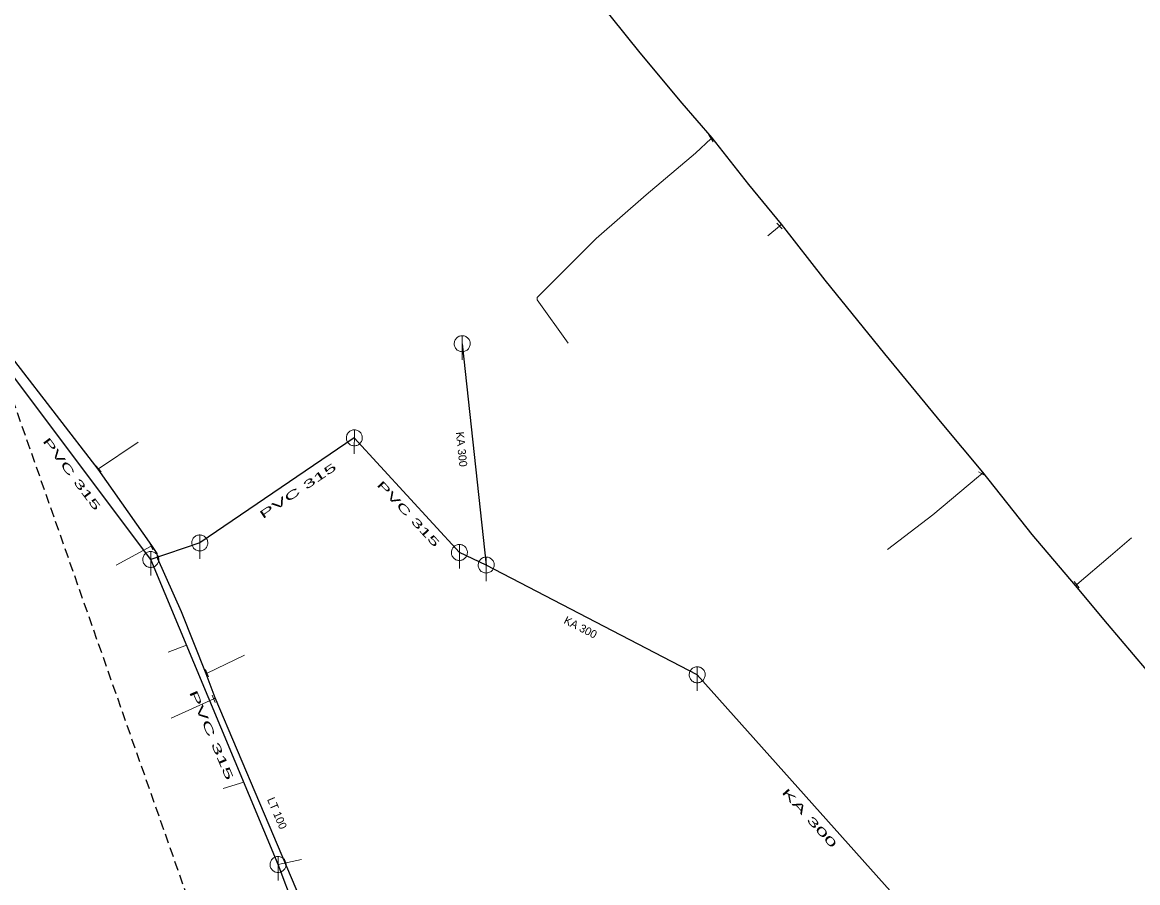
# Model space of a CAD drawing. Extents: x -659250 to -657316, y -997555 to -993684.
# Drawn here: x -658240.4 to -658101, y -996407.1 to -996299.7 of the extents above; entities that cross this region are included whole.
import ezdxf

# ---------------------------------------------------------------- set-up
doc = ezdxf.new("R2010")
doc.units = 0
doc.header["$LTSCALE"] = 0.4
doc.linetypes.add('MEDIUM_DASHED', pattern=[4.5, 3, -1.5])
doc.layers.add('1', color=7, linetype='Continuous')
for name, color, linetype, lineweight in [('11', 7, 'Continuous', 13), ('13', 7, 'Continuous', 13), ('14', 7, 'Continuous', 25), ('17', 7, 'Continuous', 25), ('22', 7, 'Continuous', 13), ('34', 7, 'Continuous', 13), ('63', 7, 'MEDIUM_DASHED', 25)]:
    doc.layers.add(name, color=color, linetype=linetype, lineweight=lineweight)

msp = doc.modelspace()

# ---------------------------------------------------------------- linework, layer by layer
at = {"layer": '11'}
for p, q in [((-658222.111, -996378.361), (-658219.838, -996377.453)), ((-658215.245, -996395.376), (-658212.681, -996394.592)), ((-658205.449, -996404.236), (-658208.39, -996404.87))]:
    msp.add_line(p, q, dxfattribs=at)
at = {"layer": '13'}
for p, q in [((-658145.723, -996325.114), (-658147.197, -996326.344)), ((-658230.833, -996355.452), (-658225.859, -996352.096)), ((-658224.251, -996365.11), (-658228.635, -996367.46)), ((-658217.266, -996380.958), (-658212.598, -996378.71)), ((-658216.432, -996384.188), (-658221.767, -996386.589))]:
    msp.add_line(p, q, dxfattribs=at)
for points in [[(-658154.274, -996314.158), (-658156.236, -996315.995), (-658162.373, -996321.204), (-658168.644, -996326.682), (-658176.017, -996334.056), (-658176.017, -996334.337), (-658172.149, -996339.734)], [(-658120.421, -996356.066), (-658120.874, -996356.386), (-658126.546, -996361.206), (-658132.236, -996365.537)], [(-658108.579, -996369.897), (-658104.349, -996366.303), (-658101.715, -996364.07)]]:
    msp.add_lwpolyline(points, dxfattribs=at)
at = {"layer": '14', "lineweight": 13}
for p, q in [((-658154.151, -996314.079), (-658154.274, -996314.158)), ((-658145.489, -996324.896), (-658145.723, -996325.114)), ((-658230.887, -996355.498), (-658230.834, -996355.452)), ((-658120.304, -996355.87), (-658120.421, -996356.066)), ((-658224.153, -996365.028), (-658224.251, -996365.11)), ((-658108.715, -996370.004), (-658108.579, -996369.897)), ((-658217.364, -996381.052), (-658217.266, -996380.958)), ((-658216.25, -996384.063), (-658216.432, -996384.188))]:
    msp.add_line(p, q, dxfattribs=at)
at = {"layer": '14'}
for p, q in [((-658224.3, -996366.77), (-658244.07, -996340.44)), ((-658218.17, -996364.699), (-658224.3, -996366.77)), ((-658208.39, -996404.87), (-658224.3, -996366.77)), ((-658156.01, -996381.17), (-658182.379, -996367.46)), ((-658192.724, -996446.332), (-658208.39, -996404.87))]:
    msp.add_line(p, q, dxfattribs=at)
for points in [[(-658185.379, -996339.809), (-658182.379, -996367.46), (-658185.73, -996365.89)], [(-658185.73, -996365.89), (-658198.859, -996351.57), (-658218.17, -996364.699)], [(-658102.699, -996440.03), (-658128.059, -996412.449), (-658156.01, -996381.17)]]:
    msp.add_lwpolyline(points, dxfattribs=at)
at = {"layer": '17'}
for points in [[(-658099.838, -996380.568), (-658104.721, -996374.813), (-658108.715, -996370.004), (-658114.16, -996363.631), (-658120.304, -996355.87), (-658125.403, -996349.761), (-658132.55, -996341.083), (-658140.008, -996331.868), (-658145.489, -996324.896), (-658149.55, -996319.91), (-658154.151, -996314.079), (-658157.877, -996309.767), (-658163.125, -996303.473), (-658168.581, -996296.64)], [(-658187.677, -996452.73), (-658187.756, -996452.037), (-658193.366, -996439.601), (-658202.822, -996415.717), (-658204.513, -996411.723), (-658210.651, -996397.227), (-658216.25, -996384.063), (-658217.364, -996381.052), (-658220.46, -996373.316), (-658223.436, -996366.695), (-658223.489, -996366.02), (-658224.153, -996365.028), (-658230.886, -996355.498), (-658241.289, -996342), (-658242.23, -996340.93)]]:
    msp.add_lwpolyline(points, dxfattribs=at)
at = {"layer": '22'}
for p, q in [((-658185.379, -996341.809), (-658185.378, -996338.809)), ((-658198.859, -996353.57), (-658198.858, -996350.57)), ((-658218.17, -996366.699), (-658218.169, -996363.699)), ((-658224.3, -996368.77), (-658224.299, -996365.77)), ((-658185.73, -996367.89), (-658185.729, -996364.89)), ((-658182.379, -996369.46), (-658182.378, -996366.46)), ((-658156.01, -996383.17), (-658156.009, -996380.17)), ((-658208.39, -996406.87), (-658208.389, -996403.87))]:
    msp.add_line(p, q, dxfattribs=at)
for points in [[(-658184.379, -996339.809), (-658184.384, -996339.7), (-658184.402, -996339.592), (-658184.432, -996339.486), (-658184.472, -996339.385), (-658184.524, -996339.288), (-658184.586, -996339.198), (-658184.658, -996339.115), (-658184.738, -996339.041), (-658184.826, -996338.975), (-658184.92, -996338.92), (-658185.02, -996338.875), (-658185.125, -996338.842), (-658185.232, -996338.82), (-658185.341, -996338.81), (-658185.451, -996338.812), (-658185.559, -996338.826), (-658185.666, -996338.851), (-658185.769, -996338.888), (-658185.867, -996338.937), (-658185.959, -996338.995), (-658186.045, -996339.064), (-658186.122, -996339.141), (-658186.191, -996339.227), (-658186.25, -996339.319), (-658186.298, -996339.417), (-658186.335, -996339.52), (-658186.361, -996339.627), (-658186.375, -996339.735), (-658186.378, -996339.845), (-658186.368, -996339.954), (-658186.347, -996340.061), (-658186.313, -996340.165), (-658186.269, -996340.265), (-658186.214, -996340.36), (-658186.148, -996340.448), (-658186.074, -996340.528), (-658185.991, -996340.6), (-658185.901, -996340.662), (-658185.805, -996340.714), (-658185.703, -996340.755), (-658185.598, -996340.785), (-658185.49, -996340.803), (-658185.38, -996340.809), (-658185.271, -996340.803), (-658185.163, -996340.785), (-658185.058, -996340.756), (-658184.956, -996340.715), (-658184.859, -996340.663), (-658184.769, -996340.601), (-658184.686, -996340.53), (-658184.611, -996340.45), (-658184.546, -996340.362), (-658184.49, -996340.268), (-658184.446, -996340.168), (-658184.412, -996340.064), (-658184.39, -996339.956), (-658184.38, -996339.847)], [(-658197.859, -996351.57), (-658197.864, -996351.461), (-658197.882, -996351.353), (-658197.912, -996351.247), (-658197.952, -996351.146), (-658198.004, -996351.049), (-658198.066, -996350.959), (-658198.138, -996350.876), (-658198.218, -996350.802), (-658198.306, -996350.736), (-658198.4, -996350.681), (-658198.5, -996350.636), (-658198.605, -996350.603), (-658198.712, -996350.581), (-658198.821, -996350.571), (-658198.931, -996350.573), (-658199.039, -996350.587), (-658199.146, -996350.612), (-658199.249, -996350.649), (-658199.347, -996350.698), (-658199.439, -996350.756), (-658199.525, -996350.825), (-658199.602, -996350.902), (-658199.671, -996350.988), (-658199.73, -996351.08), (-658199.778, -996351.178), (-658199.815, -996351.281), (-658199.841, -996351.388), (-658199.855, -996351.496), (-658199.858, -996351.606), (-658199.848, -996351.715), (-658199.827, -996351.822), (-658199.793, -996351.926), (-658199.749, -996352.026), (-658199.694, -996352.121), (-658199.628, -996352.209), (-658199.554, -996352.289), (-658199.471, -996352.361), (-658199.381, -996352.423), (-658199.285, -996352.475), (-658199.183, -996352.516), (-658199.078, -996352.546), (-658198.97, -996352.564), (-658198.86, -996352.57), (-658198.751, -996352.564), (-658198.643, -996352.546), (-658198.538, -996352.517), (-658198.436, -996352.476), (-658198.339, -996352.424), (-658198.249, -996352.362), (-658198.166, -996352.291), (-658198.091, -996352.211), (-658198.026, -996352.123), (-658197.97, -996352.029), (-658197.926, -996351.929), (-658197.892, -996351.825), (-658197.87, -996351.717), (-658197.86, -996351.608)], [(-658217.17, -996364.699), (-658217.175, -996364.59), (-658217.193, -996364.482), (-658217.223, -996364.376), (-658217.263, -996364.275), (-658217.315, -996364.178), (-658217.377, -996364.088), (-658217.449, -996364.005), (-658217.529, -996363.931), (-658217.617, -996363.865), (-658217.711, -996363.81), (-658217.811, -996363.765), (-658217.916, -996363.732), (-658218.023, -996363.71), (-658218.132, -996363.7), (-658218.242, -996363.702), (-658218.35, -996363.716), (-658218.457, -996363.741), (-658218.56, -996363.778), (-658218.658, -996363.827), (-658218.75, -996363.885), (-658218.836, -996363.954), (-658218.913, -996364.031), (-658218.982, -996364.117), (-658219.041, -996364.209), (-658219.089, -996364.307), (-658219.126, -996364.41), (-658219.152, -996364.517), (-658219.166, -996364.625), (-658219.169, -996364.735), (-658219.159, -996364.844), (-658219.138, -996364.951), (-658219.104, -996365.055), (-658219.06, -996365.155), (-658219.005, -996365.25), (-658218.939, -996365.338), (-658218.865, -996365.418), (-658218.782, -996365.49), (-658218.692, -996365.552), (-658218.596, -996365.604), (-658218.494, -996365.645), (-658218.389, -996365.675), (-658218.281, -996365.693), (-658218.171, -996365.699), (-658218.062, -996365.693), (-658217.954, -996365.675), (-658217.849, -996365.646), (-658217.747, -996365.605), (-658217.65, -996365.553), (-658217.56, -996365.491), (-658217.477, -996365.42), (-658217.402, -996365.34), (-658217.337, -996365.252), (-658217.281, -996365.158), (-658217.237, -996365.058), (-658217.203, -996364.954), (-658217.181, -996364.846), (-658217.171, -996364.737)], [(-658223.3, -996366.77), (-658223.305, -996366.661), (-658223.323, -996366.553), (-658223.353, -996366.447), (-658223.393, -996366.346), (-658223.445, -996366.249), (-658223.507, -996366.159), (-658223.579, -996366.076), (-658223.659, -996366.002), (-658223.747, -996365.936), (-658223.841, -996365.881), (-658223.941, -996365.836), (-658224.046, -996365.803), (-658224.153, -996365.781), (-658224.262, -996365.771), (-658224.372, -996365.773), (-658224.48, -996365.787), (-658224.587, -996365.812), (-658224.69, -996365.849), (-658224.788, -996365.898), (-658224.88, -996365.956), (-658224.966, -996366.025), (-658225.043, -996366.102), (-658225.112, -996366.188), (-658225.171, -996366.28), (-658225.219, -996366.378), (-658225.256, -996366.481), (-658225.282, -996366.588), (-658225.296, -996366.696), (-658225.299, -996366.806), (-658225.289, -996366.915), (-658225.268, -996367.022), (-658225.234, -996367.126), (-658225.19, -996367.226), (-658225.135, -996367.321), (-658225.069, -996367.409), (-658224.995, -996367.489), (-658224.912, -996367.561), (-658224.822, -996367.623), (-658224.726, -996367.675), (-658224.624, -996367.716), (-658224.519, -996367.746), (-658224.411, -996367.764), (-658224.301, -996367.77), (-658224.192, -996367.764), (-658224.084, -996367.746), (-658223.979, -996367.717), (-658223.877, -996367.676), (-658223.78, -996367.624), (-658223.69, -996367.562), (-658223.607, -996367.491), (-658223.532, -996367.411), (-658223.467, -996367.323), (-658223.411, -996367.229), (-658223.367, -996367.129), (-658223.333, -996367.025), (-658223.311, -996366.917), (-658223.301, -996366.808)], [(-658184.73, -996365.89), (-658184.735, -996365.781), (-658184.753, -996365.673), (-658184.783, -996365.567), (-658184.823, -996365.466), (-658184.875, -996365.369), (-658184.937, -996365.279), (-658185.009, -996365.196), (-658185.089, -996365.122), (-658185.177, -996365.056), (-658185.271, -996365.001), (-658185.371, -996364.956), (-658185.476, -996364.923), (-658185.583, -996364.901), (-658185.692, -996364.891), (-658185.802, -996364.893), (-658185.91, -996364.907), (-658186.017, -996364.932), (-658186.12, -996364.969), (-658186.218, -996365.018), (-658186.31, -996365.076), (-658186.396, -996365.145), (-658186.473, -996365.222), (-658186.542, -996365.308), (-658186.601, -996365.4), (-658186.649, -996365.498), (-658186.686, -996365.601), (-658186.712, -996365.708), (-658186.726, -996365.816), (-658186.729, -996365.926), (-658186.719, -996366.035), (-658186.698, -996366.142), (-658186.664, -996366.246), (-658186.62, -996366.346), (-658186.565, -996366.441), (-658186.499, -996366.529), (-658186.425, -996366.609), (-658186.342, -996366.681), (-658186.252, -996366.743), (-658186.156, -996366.795), (-658186.054, -996366.836), (-658185.949, -996366.866), (-658185.841, -996366.884), (-658185.731, -996366.89), (-658185.622, -996366.884), (-658185.514, -996366.866), (-658185.409, -996366.837), (-658185.307, -996366.796), (-658185.21, -996366.744), (-658185.12, -996366.682), (-658185.037, -996366.611), (-658184.962, -996366.531), (-658184.897, -996366.443), (-658184.841, -996366.349), (-658184.797, -996366.249), (-658184.763, -996366.145), (-658184.741, -996366.037), (-658184.731, -996365.928)], [(-658181.379, -996367.46), (-658181.384, -996367.351), (-658181.402, -996367.243), (-658181.432, -996367.137), (-658181.472, -996367.036), (-658181.524, -996366.939), (-658181.586, -996366.849), (-658181.658, -996366.766), (-658181.738, -996366.692), (-658181.826, -996366.626), (-658181.92, -996366.571), (-658182.02, -996366.526), (-658182.125, -996366.493), (-658182.232, -996366.471), (-658182.341, -996366.461), (-658182.451, -996366.463), (-658182.559, -996366.477), (-658182.666, -996366.502), (-658182.769, -996366.539), (-658182.867, -996366.588), (-658182.959, -996366.646), (-658183.045, -996366.715), (-658183.122, -996366.792), (-658183.191, -996366.878), (-658183.25, -996366.97), (-658183.298, -996367.068), (-658183.335, -996367.171), (-658183.361, -996367.278), (-658183.375, -996367.386), (-658183.378, -996367.496), (-658183.368, -996367.605), (-658183.347, -996367.712), (-658183.313, -996367.816), (-658183.269, -996367.916), (-658183.214, -996368.011), (-658183.148, -996368.099), (-658183.074, -996368.179), (-658182.991, -996368.251), (-658182.901, -996368.313), (-658182.805, -996368.365), (-658182.703, -996368.406), (-658182.598, -996368.436), (-658182.49, -996368.454), (-658182.38, -996368.46), (-658182.271, -996368.454), (-658182.163, -996368.436), (-658182.058, -996368.407), (-658181.956, -996368.366), (-658181.859, -996368.314), (-658181.769, -996368.252), (-658181.686, -996368.181), (-658181.611, -996368.101), (-658181.546, -996368.013), (-658181.49, -996367.919), (-658181.446, -996367.819), (-658181.412, -996367.715), (-658181.39, -996367.607), (-658181.38, -996367.498)], [(-658155.01, -996381.17), (-658155.015, -996381.061), (-658155.033, -996380.953), (-658155.063, -996380.847), (-658155.103, -996380.746), (-658155.155, -996380.649), (-658155.217, -996380.559), (-658155.289, -996380.476), (-658155.369, -996380.402), (-658155.457, -996380.336), (-658155.551, -996380.281), (-658155.651, -996380.236), (-658155.756, -996380.203), (-658155.863, -996380.181), (-658155.972, -996380.171), (-658156.082, -996380.173), (-658156.19, -996380.187), (-658156.297, -996380.212), (-658156.4, -996380.249), (-658156.498, -996380.298), (-658156.59, -996380.356), (-658156.676, -996380.425), (-658156.753, -996380.502), (-658156.822, -996380.588), (-658156.881, -996380.68), (-658156.929, -996380.778), (-658156.966, -996380.881), (-658156.992, -996380.988), (-658157.006, -996381.096), (-658157.009, -996381.206), (-658156.999, -996381.315), (-658156.978, -996381.422), (-658156.944, -996381.526), (-658156.9, -996381.626), (-658156.845, -996381.721), (-658156.779, -996381.809), (-658156.705, -996381.889), (-658156.622, -996381.961), (-658156.532, -996382.023), (-658156.436, -996382.075), (-658156.334, -996382.116), (-658156.229, -996382.146), (-658156.121, -996382.164), (-658156.011, -996382.17), (-658155.902, -996382.164), (-658155.794, -996382.146), (-658155.689, -996382.117), (-658155.587, -996382.076), (-658155.49, -996382.024), (-658155.4, -996381.962), (-658155.317, -996381.891), (-658155.242, -996381.811), (-658155.177, -996381.723), (-658155.121, -996381.629), (-658155.077, -996381.529), (-658155.043, -996381.425), (-658155.021, -996381.317), (-658155.011, -996381.208)], [(-658207.39, -996404.87), (-658207.395, -996404.761), (-658207.413, -996404.653), (-658207.443, -996404.547), (-658207.483, -996404.446), (-658207.535, -996404.349), (-658207.597, -996404.259), (-658207.669, -996404.176), (-658207.749, -996404.102), (-658207.837, -996404.036), (-658207.931, -996403.981), (-658208.031, -996403.936), (-658208.136, -996403.903), (-658208.243, -996403.881), (-658208.352, -996403.871), (-658208.462, -996403.873), (-658208.57, -996403.887), (-658208.677, -996403.912), (-658208.78, -996403.949), (-658208.878, -996403.998), (-658208.97, -996404.056), (-658209.056, -996404.125), (-658209.133, -996404.202), (-658209.202, -996404.288), (-658209.261, -996404.38), (-658209.309, -996404.478), (-658209.346, -996404.581), (-658209.372, -996404.688), (-658209.386, -996404.796), (-658209.389, -996404.906), (-658209.379, -996405.015), (-658209.358, -996405.122), (-658209.324, -996405.226), (-658209.28, -996405.326), (-658209.225, -996405.421), (-658209.159, -996405.509), (-658209.085, -996405.589), (-658209.002, -996405.661), (-658208.912, -996405.723), (-658208.816, -996405.775), (-658208.714, -996405.816), (-658208.609, -996405.846), (-658208.501, -996405.864), (-658208.391, -996405.87), (-658208.282, -996405.864), (-658208.174, -996405.846), (-658208.069, -996405.817), (-658207.967, -996405.776), (-658207.87, -996405.724), (-658207.78, -996405.662), (-658207.697, -996405.591), (-658207.622, -996405.511), (-658207.557, -996405.423), (-658207.501, -996405.329), (-658207.457, -996405.229), (-658207.423, -996405.125), (-658207.401, -996405.017), (-658207.391, -996404.908)]]:
    msp.add_lwpolyline(points, close=True, dxfattribs=at)
at = {"layer": '34'}
for p, q in [((-658154.003, -996314.578), (-658154.543, -996313.737)), ((-658145.381, -996325.479), (-658146.063, -996324.747)), ((-658231.161, -996355.074), (-658230.505, -996355.829)), ((-658119.992, -996356.324), (-658120.848, -996355.806)), ((-658224.057, -996365.571), (-658224.443, -996364.648)), ((-658108.888, -996369.504), (-658108.27, -996370.29)), ((-658217.072, -996381.419), (-658217.458, -996380.496)), ((-658216.238, -996384.649), (-658216.624, -996383.726))]:
    msp.add_line(p, q, dxfattribs=at)
at = {"layer": '63'}
msp.add_lwpolyline([(-659116.685, -993855.266), (-658551.464, -993848.288), (-658551.464, -993848.288), (-657316.352, -997490.822), (-657316.352, -997490.822), (-657839.705, -997490.822), (-657839.705, -997490.822)], close=True, dxfattribs=at)

# ---------------------------------------------------------------- texts
at = {"layer": '1'}
for s, rotation, width, p in [('PVC 315 ', 307, 2.05, (-658237.873, -996351.997)), ('PVC 315 ', 34, 2.1, (-658210.292, -996361.744)), ('PVC 315 ', 313, 2, (-658196.122, -996357.491)), ('PVC 315 ', 293, 2.25, (-658219.525, -996383.354)), ('KA 300', 312, 2.15, (-658145.513, -996395.895))]:
    msp.add_text(s, height=1, rotation=rotation, dxfattribs=dict(at, width=width)).set_placement(p)
for s, rotation, p in [('KA 300', 276, (-658186.176, -996350.866)), ('KA 300', 333, (-658172.772, -996374.691)), ('LT 100', 293, (-658209.787, -996396.737))]:
    msp.add_text(s, height=1, rotation=rotation, dxfattribs=at).set_placement(p)

doc.saveas('drawing.dxf')
